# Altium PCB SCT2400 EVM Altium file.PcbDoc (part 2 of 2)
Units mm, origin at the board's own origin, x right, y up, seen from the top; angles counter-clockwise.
Board outline 45.2 x 80.2 mm, 4 copper layers (Top Layer, Signal Layer 1, Signal Layer 2, Bottom Layer), stack 0.778 mm thick; 165 components, 146 nets, 619 pads, 674 vias.
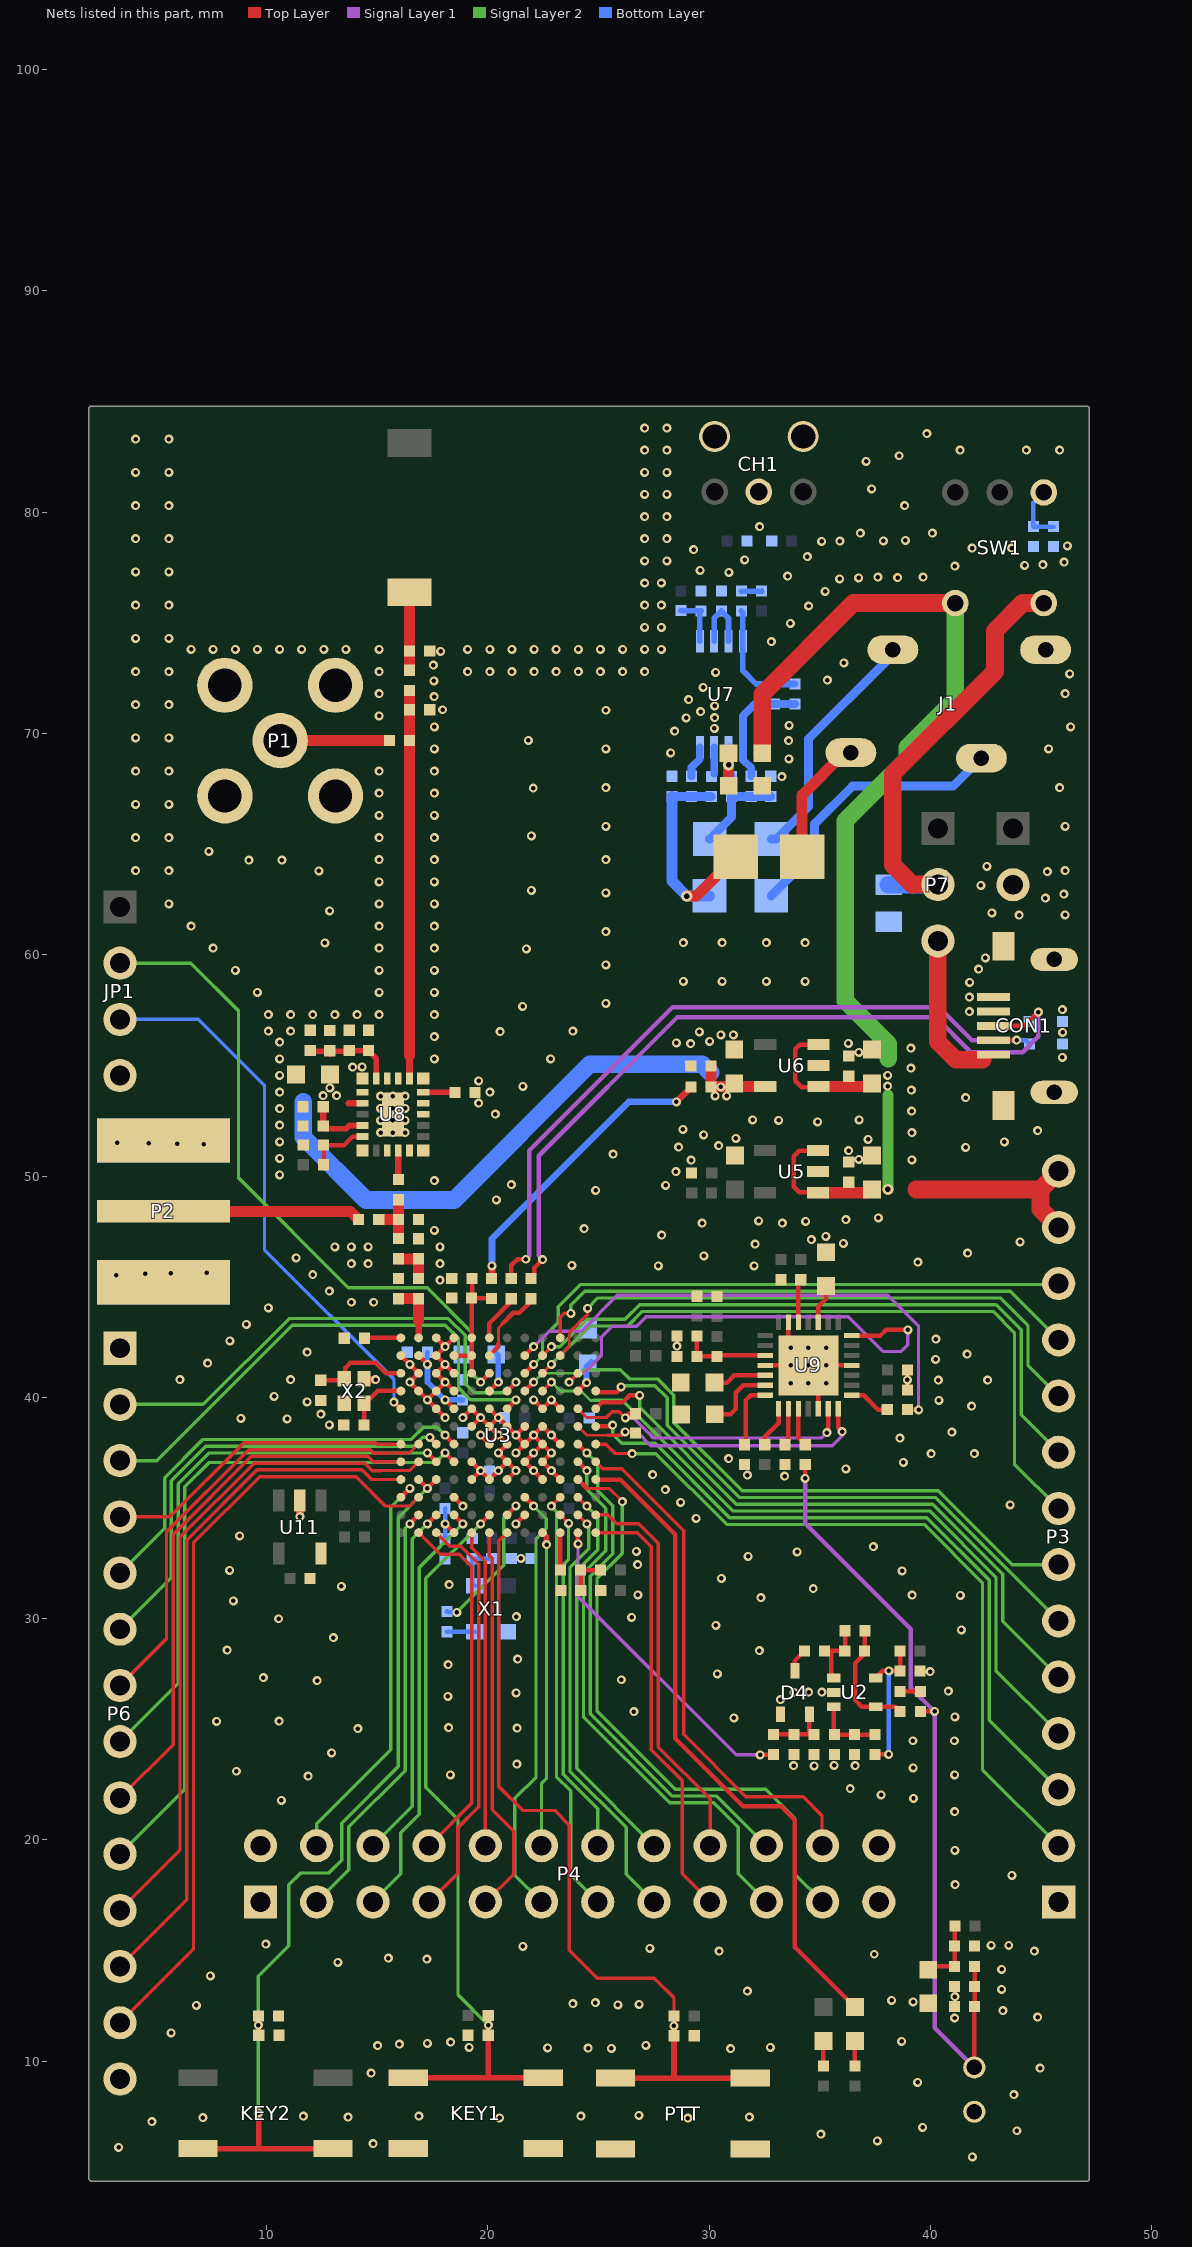
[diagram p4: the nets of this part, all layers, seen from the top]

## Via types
v1: diameter 0.406, hole 0.203, Top Layer to Bottom Layer, tented both sides, 667 vias
v2: diameter 0.406, hole 0.203, Top Layer to Bottom Layer, tented top, 4 vias
v3: diameter 0.508, hole 0.254, Top Layer to Bottom Layer, tented both sides, 3 vias

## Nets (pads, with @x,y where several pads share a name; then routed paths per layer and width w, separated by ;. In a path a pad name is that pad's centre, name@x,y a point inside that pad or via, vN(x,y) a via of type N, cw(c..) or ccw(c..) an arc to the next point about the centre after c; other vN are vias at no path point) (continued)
GND: C2.2 C3.1 C4.2 C7.1 C9.1 C11.1 C12.1 C13.2 C16.2 C17.1 C18.2 C19.2 C21.2 C22.1 C23.2 C24.2 C25.2 C26.2 C27.2 C28.2 C29.2 C31.2 C32.2 C33.2 C34.1 C35.2 C36.2 C37.1 C39.2 C41.1 C43.2 C50.2 C53.2 C54.2 C55.2 C56.2 C57.2 C58.2 C59.2 C60.1 C61.1 C66.1 C67.1 C68.1 C69.1 C70.1 C71.2 C72.1 C73.2 C74.1 C75.2 C76.2 C77.1 C78.2 C88.2 C89.2 C90.2 C95.2 C96.2 C97.1 C99.1 C100.2 C104.2 C105.2 C106.1 C107.2 C108.1 C111.1 C112.1 C113.2 C114.1 C115.1 CH1.2 CH1.4 CH1.5 CON1.4 CON1.5 CON1.6 D2.1 D3.1 D4.1 DC5V.2 J1.1 JP1.4 KEY1.2 MIC1.2 P1.2 P2.2 P3.1 P4.1 P4.2 P4.23 P4.24 P6.1 P6.14 PTT.2 R3.2 R4.2 R12.1 R24.2 R34.1 R40.1 U2.2 U3.A11 U3.B9 U3.B10 U3.C8 U3.C9 U3.C10 U3.C11 U3.C12 U3.D3 U3.D9 U3.D10 U3.D12 U3.E4 U3.E5 U3.E7 U3.E8 U3.F4 U3.F6 U3.F7 U3.F8 U3.G4 U3.G5 U3.G6 U3.G7 U3.H2 U3.H5 U3.H6 U3.H7 U3.J4 U3.J5 U3.J6 U3.J7 U3.J8 U3.K4 U3.K6 U3.K8 U5.2 U6.2 U7.7 U8.0 U8.1 U8.4 U8.5 U8.7 U8.9 U8.10 U8.12 U8.13 U8.18 U8.20 U8.22 U9.4 U9.13 U9.18 U9.26 U9.29 U11.2 U11.5 X1.2 X2.2 X2.4 | length 44.1
  Top Layer w0.203: U3.A11@16.068,41.888 v1(16.468,41.488) U3.B10@16.868,41.088 v1(16.468,40.688) U3.B9@16.868,40.288 v1(17.268,39.888) ; U3.C12@17.668,42.688 v1(18.068,42.288) ; v1(18.068,39.088) U3.C8@17.668,39.488 v1(17.268,39.888) ; U3.D3@18.468,35.488 v1(18.868,35.088) ; U3.D9@18.468,40.288 v1(18.068,40.688) ; U3.D10@18.468,41.088 v1(18.068,41.488) ; U3.D12@18.468,42.688 v1(18.068,42.288) ; v1(18.868,39.088) U3.E8@19.268,39.488 v1(19.668,39.088) ; U3.E4@19.268,36.288 v1(19.668,36.688) ; U3.E5@19.268,37.088 v1(19.668,36.688) ; U3.E7@19.268,38.688 v1(19.668,39.088) ; v1(19.668,38.288) U3.F6@20.068,37.888 v1(20.468,38.288) ; U3.F8@20.068,39.488 v1(20.468,39.088) ; U3.G4@20.868,36.288 v1(21.268,36.688) v1(20.468,37.488) U3.G6@20.868,37.888 v1(20.468,38.288) ; U3.G5@20.868,37.088 v1(20.468,36.688) U3.F4@20.068,36.288 v1(19.668,36.688) ; v1(21.268,34.288) U3.H2@21.668,34.688 ; v1(21.268,37.488) U3.H6@21.668,37.888 ; U3.H7@21.668,38.688 v1(21.268,38.288) ; v1(22.068,39.888) U3.J8@22.468,39.488 v1(22.868,39.888) ; U3.J4@22.468,36.288 v1(22.068,36.688) U3.H5@21.668,37.088 v1(22.068,37.488) U3.J6@22.468,37.888 ; v1(22.868,37.488) U3.J5@22.468,37.088 v1(22.868,36.688) U3.K4@23.268,36.288 ; v1(22.868,37.488) U3.J6@22.468,37.888 ; v1(22.868,39.888) U3.K8@23.268,39.488 ; U3.K6@23.268,37.888 v1(22.868,38.288) U3.J7@22.468,38.688 v1(22.068,38.288) ; U9.18@32.53,41.444 v1(34.48,41.444) ; U9.13@33.58,43.394 33.58,42.344 v1(34.48,41.444) ; U9.26@34.93,39.494 34.93,40.994 v1(34.48,41.444) ; U9.4@36.43,41.444 v1(34.48,41.444) ; v1(17.268,39.888) U3.C9@17.668,40.288 v1(18.068,40.688) ; v1(18.068,40.688) U3.C10@17.668,41.088 v1(18.068,41.488) ; v1(18.068,41.488) U3.C11@17.668,41.888 v1(18.068,42.288) ; v1(19.668,39.088) U3.F7@20.068,38.688 ; U3.F7@20.068,38.688 v1(20.468,38.288) ; U3.F7@20.068,38.688 v1(20.468,39.088) ; v1(20.468,39.088) U3.G7@20.868,38.688 v1(21.268,38.288) ; v1(21.268,38.288) U3.H6@21.668,37.888 ; U3.H6@21.668,37.888 v1(22.068,38.288) ; v1(22.068,38.288) U3.J6@22.468,37.888
  Top Layer w0.35: v1(11.506,34.613) U11.2@11.506,35.334 ; X2.2@14.439,40.801 v1(14.925,40.801)
  Bottom Layer w0.35: C50.2@30.222,68.181 U7.7@30.222,69.372
  other v1: 41.885,5.686 3.316,6.111 14.817,6.279 37.598,6.405 35.045,6.709 43.901,6.861 39.645,7.014 4.816,7.277 20.533,7.439 29.035,7.429 7.116,7.459 13.683,7.479 31.812,7.479 11.656,7.52 16.885,7.52 24.202,7.52 26.816,7.561 43.77,8.493 39.412,9.05 14.728,9.46 44.955,9.689 25.582,10.587 30.967,10.576 22.698,10.605 24.53,10.593 19.152,10.623 32.76,10.631 15.012,10.71 27.142,10.716 15.996,10.778 17.259,10.809 18.317,10.871 38.693,10.894 5.687,11.28 41.089,11.956 44.834,11.999 43.271,12.288 6.822,12.526 25.867,12.554 26.832,12.573 23.843,12.604 24.852,12.65 39.215,12.683 38.247,12.749 41.097,12.924 31.721,13.175 43.21,13.245 7.461,13.864 43.216,14.158 13.217,14.472 17.238,14.621 15.499,14.665 37.456,14.836 30.444,14.978 44.692,14.978 27.323,15.1 21.574,15.193 42.742,15.242 43.534,15.243 9.964,15.292 41.115,17.988 43.678,18.404 41.104,19.528 41.084,21.281 10.663,21.788 39.23,21.879 37.77,22.042 36.372,22.325 11.879,22.883 18.304,22.943 41.084,22.943 8.636,23.106 39.21,23.253 33.813,23.364 34.741,23.349 36.595,23.359 35.642,23.369 21.303,23.43 12.933,23.936 39.199,24.484 41.074,24.484 14.129,25.031 21.324,25.051 18.223,25.071 7.745,25.355 10.562,25.375 31.113,25.517 41.094,25.568 26.593,25.801 33.215,26.338 18.192,26.49 21.273,26.642 33.823,26.667 34.487,26.683 35.095,26.683 40.806,26.728 12.285,27.2 26.026,27.24 9.853,27.342 30.363,27.504 39.984,27.608 18.202,27.929 21.344,28.172 32.268,28.557 8.211,28.578 13.014,29.145 41.388,29.49 30.302,29.692 10.541,29.996 26.492,30.057 21.283,30.088 8.501,30.809 32.329,30.949 39.169,31.06 41.348,31.05 26.774,31.078 34.7,31.354 13.379,31.456 18.248,31.542 30.545,31.82 38.713,32.165 8.332,32.185 26.764,32.447 21.488,32.72 31.761,32.814 33.97,33.016 26.703,33.044 37.416,33.259 8.778,33.746 29.407,34.536 43.597,35.144 28.707,35.26 28.014,35.836 33.405,36.442 31.718,36.485 27.445,36.51 36.179,36.765 38.775,37.06 30.878,37.23 40.03,37.455 41.976,37.455 38.611,38.16 40.962,38.428 12.835,38.753 10.922,39.03 8.834,39.048 12.453,39.238 41.854,39.603 11.834,39.798 40.375,39.867 10.334,40.048 33.68,40.644 34.48,40.644 35.28,40.644 38.951,40.786 40.355,40.779 42.584,40.779 6.084,40.798 11.084,40.798 33.68,41.444 35.28,41.444 7.334,41.548 40.233,41.721 41.652,41.954 11.834,42.048 33.68,42.244 34.48,42.244 35.28,42.244 28.543,42.318 8.334,42.548 40.243,42.633 9.084,43.298 10.084,44.048 13.834,44.298 14.834,44.298 12.834,44.798 17.834,45.298 3.215,45.521 12.084,45.548 4.522,45.592 5.677,45.612 7.299,45.622 32.025,45.937 23.796,45.967 27.699,45.946 13.834,46.048 14.584,46.048 17.834,46.048 39.422,46.109 11.334,46.298 29.755,46.393 41.672,46.514 13.084,46.798 13.834,46.798 14.584,46.798 17.834,46.798 32.076,46.929 36.058,46.96 44.043,47.021 34.614,47.127 35.273,47.269 27.853,47.333 17.584,47.548 24.343,47.629 29.674,47.872 33.306,47.878 32.227,47.973 34.355,47.953 36.179,48.034 37.639,48.115 20.386,48.923 24.87,49.352 28.029,49.584 21.058,49.611 17.584,49.798 10.584,50.048 28.488,50.203 29.187,50.725 39.159,50.73 36.762,50.755 10.584,50.798 25.661,50.993 36.301,51.15 41.584,51.298 28.62,51.307 30.424,51.378 7.157,51.439 4.684,51.48 5.961,51.459 3.245,51.5 10.584,51.548 43.334,51.548 37.178,51.657 31.204,51.703 29.744,51.865 15.155,51.961 15.705,51.961 16.255,51.961 39.159,51.966 44.834,52.048 28.812,52.108 10.584,52.298 34.893,52.453 15.155,52.511 15.705,52.511 16.255,52.511 33.139,52.513 31.964,52.534 36.767,52.544 20.334,52.798 39.144,52.934 10.584,53.048 15.155,53.061 15.705,53.061 16.255,53.061 19.584,53.298 41.584,53.548 15.155,53.611 15.705,53.611 16.255,53.611 10.584,53.798 20.084,53.798 39.138,53.887 21.584,54.048 19.584,54.298 10.584,54.548 39.113,54.874 13.885,54.925 14.317,54.931 10.584,55.298 17.584,55.298 22.834,55.298 45.959,55.361 36.757,55.589 39.108,55.781 29.163,55.983 36.286,55.994 28.519,56.016 10.584,56.048 30.021,56.082 17.584,56.298 30.53,56.377 31.092,56.374 45.963,56.496 20.551,56.528 29.559,56.517 10.084,56.548 11.084,56.548 23.834,56.548 10.084,57.298 11.084,57.298 12.084,57.298 13.084,57.298 14.084,57.298 15.084,57.298 17.584,57.298 41.756,57.434 45.959,57.524 21.564,57.672 25.334,57.798 41.759,58.084 9.584,58.298 15.084,58.298 17.584,58.298 41.77,58.754 28.834,58.798 30.584,58.798 32.584,58.798 34.334,58.798 8.584,59.298 15.084,59.298 17.584,59.298 42.177,59.351 25.334,59.548 42.479,59.857 21.739,60.269 7.584,60.298 15.084,60.298 17.584,60.298 12.628,60.534 28.834,60.548 30.584,60.548 32.584,60.548 34.334,60.548 25.334,61.048 6.584,61.298 15.084,61.298 17.584,61.298 44.003,61.786 46.084,61.798 42.766,61.897 12.848,61.986 5.584,62.298 15.084,62.298 17.584,62.298 45.188,62.556 46.019,62.738 25.334,62.798 21.96,62.911 42.27,63.134 15.084,63.298 17.584,63.298 45.28,63.762 4.084,63.798 5.584,63.798 12.364,63.791 46.084,63.798 42.543,63.995 9.194,64.275 10.691,64.275 15.084,64.298 17.584,64.298 25.334,64.298 7.389,64.671 4.084,65.298 5.584,65.298 15.084,65.298 17.584,65.298 21.96,65.376 25.334,65.798 46.084,65.798 15.084,66.298 17.584,66.298 4.084,66.798 5.584,66.798 15.084,67.298 17.584,67.298 22.048,67.533 25.334,67.548 45.834,67.548 33.284,68.049 4.084,68.298 5.584,68.298 15.084,68.298 17.584,68.298 33.603,68.848 28.26,69.123 17.584,69.298 25.334,69.298 45.334,69.298 21.828,69.69 33.586,69.678 4.084,69.798 5.584,69.798 28.436,70.102 30.232,70.226 17.584,70.298 46.334,70.298 33.614,70.366 28.953,70.702 30.238,70.712 15.084,70.798 29.608,70.983 25.334,71.048 17.954,71.071 30.238,71.244 4.084,71.298 5.584,71.298 29.069,71.527 17.564,71.661 15.084,71.798 46.084,71.798 29.729,72.083 17.554,72.375 35.342,72.408 46.286,72.694 30.29,72.76 4.084,72.798 5.584,72.798 15.084,72.798 19.084,72.798 20.084,72.798 21.084,72.798 22.084,72.798 23.084,72.798 24.084,72.798 25.084,72.798 26.084,72.798 27.084,72.798 17.539,73.09 36.079,73.189 17.858,73.708 6.584,73.798 7.584,73.798 8.584,73.798 9.584,73.798 10.584,73.798 11.584,73.798 12.584,73.798 13.584,73.798 15.084,73.798 19.084,73.798 20.084,73.798 21.084,73.798 22.084,73.798 23.084,73.798 24.084,73.798 25.084,73.798 26.084,73.798 27.084,73.798 27.834,73.798 32.811,74.147 4.084,74.298 5.584,74.298 27.084,74.798 27.834,74.798 33.669,74.972 34.489,75.759 4.084,75.798 5.584,75.798 27.084,75.798 27.834,75.798 35.232,76.425 27.084,76.798 27.834,76.798 35.887,76.981 36.751,77.03 38.517,77.041 37.62,77.068 39.667,77.069 33.537,77.112 30.885,77.283 4.084,77.298 5.584,77.298 29.592,77.366 41.097,77.558 44.256,77.597 45.081,77.63 46.033,77.74 27.084,77.798 28.084,77.798 31.6,77.844 34.439,77.987 29.295,78.307 41.879,78.373 43.662,78.373 46.187,78.472 35.083,78.675 35.903,78.692 37.873,78.703 38.863,78.725 4.084,78.798 5.584,78.798 27.084,78.798 28.084,78.798 36.834,79.048 40.084,79.048 32.271,79.346 27.084,79.798 28.084,79.798 4.084,80.298 5.584,80.298 38.834,80.298 27.084,80.798 28.084,80.798 37.334,81.048 4.084,81.798 5.584,81.798 27.084,81.798 28.084,81.798 37.084,82.298 38.584,82.548 27.084,82.798 28.084,82.798 41.334,82.798 44.334,82.798 45.834,82.798 4.084,83.298 5.584,83.298 39.834,83.548 27.084,83.798 28.084,83.798
IIC_SCK: R19.2 U3.L7 U9.28 | length 14.4
  Top Layer w0.127: U3.L7@24.068,38.688 24.471,38.285 25.395,38.285
  Top Layer w0.152: 25.395,38.285 26.052,38.285 v1(26.203,38.436)
  Top Layer w0.203: v1(26.203,38.436) 26.623,38.436 R19.2@26.669,38.39 ; U9.28@35.83,39.494 35.83,38.625 v1(36.005,38.451)
  Signal Layer 1 w0.152: v1(26.203,38.436) 26.741,38.436 27.358,37.819 35.557,37.819 36.005,38.267 v1(36.005,38.451)
IIC_SDA: R20.2 U3.L8 U9.27 | length 13.8
  Top Layer w0.127: U3.L8@24.068,39.488 24.466,39.09 25.188,39.09
  Top Layer w0.152: 25.188,39.09 25.352,39.09 25.608,39.346 25.934,39.346 v1(26.21,39.069)
  Top Layer w0.203: v1(35.32,38.403) 35.38,38.464 U9.27@35.38,39.494
  Top Layer w0.254: v1(26.21,39.069) 26.396,39.254 R20.2@26.665,39.254
  Signal Layer 1 w0.152: v1(26.21,39.069) 26.574,39.069 27.476,38.167 35.084,38.167 v1(35.32,38.403)
IN1L: C10.2 U9.24 | length 1.8
  Top Layer w0.203: U9.24@34.03,39.494 34.03,38.165 C10.2@34.338,37.858
KEY1: C89.1 KEY1.1 R13.1 U3.F2 | length 34.3
  Top Layer w0.203: v1(19.668,34.288) U3.F2@20.068,34.688
  Top Layer w0.254: KEY1.1@16.406,9.257 20.026,9.257 ; R13.1@20.011,12.068 C89.1@20.011,11.179 20.011,9.271 20.026,9.257 ; KEY1.1@22.502,9.257 20.026,9.257
  Signal Layer 2 w0.152: v1(19.668,34.288) 17.196,31.817 17.196,22.377 18.649,20.924 18.649,12.995 v1(20.015,11.629)
KEY2: C88.1 KEY2.1 R12.2 U3.B4 U3.C4 | length 42.1
  Top Layer w0.152: R12.2@9.627,11.192 R12.2@9.639,11.18
  Top Layer w0.203: U3.B4@16.868,36.288 v1(17.268,35.888) U3.C4@17.668,36.288
  Top Layer w0.254: KEY2.1@6.902,6.054 KEY2.1@12.998,6.054 ; v1@9.626,11.626 9.626,12.045 C88.1@9.627,12.047 R12.2@9.627,11.192 ; 9.637,6.169 v1(9.637,7.67)
  Signal Layer 2 w0.152: v1@9.624,7.683 v1(9.624,11.631) 9.624,13.845 11.002,15.223 11.002,17.977 11.533,18.508 12.817,18.508 13.387,19.078 13.387,20.762 15.944,23.32 15.944,34.565 v1(17.268,35.888)
MCLK: R5.1 U3.H11 | length 23.8
  Top Layer w0.203: U3.H11@21.668,41.888 v1(22.068,42.288) ; R5.1@38.96,39.447 38.973,39.434 v1(39.458,39.434)
  Signal Layer 1 w0.152: v1(22.068,42.288) 22.775,42.996 24.233,42.996 25.846,44.609 38.072,44.609 39.458,43.223 v1(39.458,39.434)
MCLK1: C15.1 U3.G2 | length 7
  Top Layer w0.203: U3.G2@20.868,34.688 21.268,35.088 v1(21.268,35.101)
  Signal Layer 2 w0.152: v1(18.601,30.29) 20.718,32.406 20.718,34.551 v1(21.268,35.101)
  Bottom Layer w0.203: C15.1@18.149,30.324 18.169,30.343 18.222,30.29 v1(18.601,30.29)
MIC: C10.1 C18.1 C38.2 C115.2 MIC1.1 R32.2 | length 35.6
  Top Layer w0.203: v1(34.328,36.34) 34.328,36.949 C10.1@34.338,36.958 ; C38.2@39.539,25.812 39.546,25.806 v1(40.182,25.806) ; MIC1.1@41.977,9.72 C18.1@41.977,12.469 41.988,12.48 C115.2@41.988,13.377 R32.2@41.988,14.292
  Signal Layer 1 w0.203: v1(34.328,36.34) 34.328,34.307 39.103,29.532 39.103,26.885 v1(40.182,25.806) 40.182,11.514 MIC1.1@41.977,9.72
NetB5_1: B5.1 C50.1 C70.2 U7.6 | length 2.8
  Top Layer w0.5: B5.1@30.875,69.103 v3(30.875,68.584) 30.875,67.637 C70.2@30.878,67.634
  Bottom Layer w0.35: U7.6@30.872,69.372 30.872,68.196 C50.1@31.004,68.064
NetB6_1: B6.1 C13.1 X1.4 | length 2.2
  Bottom Layer w0.203: X1.4@19.418,31.488 19.292,31.614 C13.1@19.292,32.712 20.165,32.712 B6.1@20.171,32.719
NetB7_1: B7.1 C91.2 R21.2 U7.5 | length 5.5
  Bottom Layer w0.35: B7.1@31.893,68.064 31.893,68.445 31.522,68.816 U7.5@31.522,69.372 31.522,70.787 32.068,71.333 C91.2@32.958,71.333 33.868,71.333 R21.2@33.875,71.34
NetB7_2: B7.2 C1.1 C94.1 C96.1 | length 4.1
  Bottom Layer w0.4: C1.1@30.019,65.228 31.004,66.214 C94.1@31.004,67.149 B7.2@31.893,67.149 C96.1@32.782,67.149
NetB8_1: B8.1 U7.8 | length 1.5
  Bottom Layer w0.35: B8.1@29.201,68.064 29.201,68.471 29.572,68.842 U7.8@29.572,69.372
NetB8_2: B8.2 C20.1 C94.2 C95.1 LS1.1 | length 10.5
  Top Layer w0.5: v3(28.984,62.651) 29.42,62.651 LS1.1@31.197,64.428
  Bottom Layer w0.4: C95.1@28.312,67.149 B8.2@29.201,67.149 C94.2@30.09,67.149
  Bottom Layer w0.5: C95.1@28.312,67.149 28.312,63.323 v3(28.984,62.651) 30,62.651 C20.1@30.01,62.661
NetC1_2: C1.2 J1.4 | length 10.8
  Bottom Layer w0.4: C1.2@32.813,65.228 33.021,65.228 34.487,66.694 34.487,69.751 38.02,73.284 J1.4@38.02,73.779
NetC6_1: C6.1 D4.3 | length 1.1
  Top Layer w0.203: D4.3@33.875,27.637 33.875,28.109 C6.1@34.306,28.541
NetC6_2: C6.2 C30.1 R36.2 U2.1 | length 3.2
  Top Layer w0.203: C6.2@35.206,28.541 35.504,28.541 ; U2.1@35.627,27.322 35.621,27.315 35.621,27.295 35.504,27.412 35.504,28.541 ; C30.1@36.135,29.456 36.135,28.552 R36.2@36.124,28.541 35.504,28.541
NetC7_2: C7.2 U9.23 | length 1.7
  Top Layer w0.203: C7.2@33.423,37.858 33.58,38.015 U9.23@33.58,39.494
NetC8_2: C8.2 U9.22 | length 1.9
  Top Layer w0.203: C8.2@32.509,37.858 32.509,38.214 33.13,38.836 U9.22@33.13,39.494
NetC9_2: C9.2 U9.21 | length 3
  Top Layer w0.203: C9.2@31.594,37.858 31.641,37.904 31.641,39.862 31.873,40.094 U9.21@32.53,40.094
NetC11_2: C11.2 R1.1 R2.2 | length 1.8
  Top Layer w0.203: C11.2@24.194,31.278 24.194,32.181 R1.1@24.183,32.192 R2.2@25.086,32.192
NetC15_2: C15.2 X1.3 | length 1.3
  Bottom Layer w0.203: C15.2@18.149,29.409 X1.3@19.418,29.408 X1.3@19.418,29.408
NetC16_1: C16.1 C114.2 U3.B11 U3.D8 | length 4.4
  Top Layer w0.203: U3.B11@16.868,41.888 v1(17.268,41.488) ; v1(18.068,39.888) U3.D8@18.468,39.488
  Bottom Layer w0.203: v1(17.268,41.488) 17.268,42.035 C114.2@17.274,42.042
  Bottom Layer w0.254: v1(17.268,41.488) 17.268,40.688 v1(18.068,39.888) 18.844,39.888 C16.1@18.849,39.883
NetC17_2: C17.2 U3.A12 | length 1.7
  Top Layer w0.203: C17.2@14.42,42.668 14.44,42.688 U3.A12@16.068,42.688
NetC19_1: C19.1 R26.2 U8.17 | length 2.8
  Top Layer w0.203: R26.2@12.57,50.512 C19.1@12.57,51.401 13.508,51.401 13.893,51.786 U8.17@14.33,51.786
NetC20_2: C20.2 J1.2 | length 12.8
  Bottom Layer w0.4: C20.2@32.804,62.661 34.751,64.608 34.751,65.901 36.477,67.627 41.018,67.627 J1.2@42.27,68.879
NetC22_2: C22.2 U3.F9 | length 1.8
  Top Layer w0.203: U3.F9@20.068,40.288 v1(20.468,40.688)
  Bottom Layer w0.254: C22.2@20.422,41.938 20.468,41.893 v1(20.468,40.688)
NetC24_1: C24.1 D4.2 R11.2 R24.1 | length 2.5
  Top Layer w0.203: R11.2@32.909,24.768 34.481,24.768 34.525,24.811 D4.2@34.525,25.687
NetC30_2: C30.2 R36.1 R39.2 U2.4 | length 5.6
  Top Layer w0.203: C30.2@37.035,29.456 37.035,28.552 R36.1@37.024,28.541 37.024,28.417 36.588,27.981 36.588,26.324 36.89,26.022 U2.4@37.527,26.022 38.415,26.022 R39.2@38.624,25.812
NetC32_1: C32.1 R37.1 R38.2 U2.5 | length 6.6
  Top Layer w0.203: R38.2@37.481,23.857 37.489,23.864 v1(38.104,23.864) ; U2.5@37.527,27.322 37.847,27.642 v1(38.113,27.642) 38.609,27.642 C32.1@38.624,27.627 R37.1@38.624,28.541
  Bottom Layer w0.203: v1(38.104,23.864) 38.113,23.873 v1(38.113,27.642)
NetC36_1: C36.1 R38.1 R40.2 U2.3 | length 3.1
  Top Layer w0.203: U2.3@35.627,26.022 35.627,24.782 C36.1@35.653,24.757 R38.1@37.481,24.757
NetC38_1: C38.1 R39.1 | length 0.9
  Top Layer w0.203: R39.1@38.624,26.712 C38.1@39.539,26.712
NetC39_1: C39.1 U7.2 U7.3 | length 3
  Bottom Layer w0.254: U7.2@30.222,74.172 30.222,75.206 C39.1@30.547,75.531 30.872,75.206 U7.3@30.872,74.172
NetC41_2: C41.2 U3.L9 | length 1.6
  Top Layer w0.203: U3.L9@24.068,40.288 24.442,40.663 v1(24.456,40.663)
  Bottom Layer w0.254: v1(24.456,40.663) 24.456,41.39 C41.2@24.68,41.614
NetC43_1: C43.1 R18.2 U3.D1 | length 1.9
  Top Layer w0.203: v1(18.068,34.288) U3.D1@18.468,33.888
  Bottom Layer w0.203: C43.1@18.062,33.609 18.068,33.615 v1(18.068,34.288) 18.068,34.975 R18.2@18.062,34.981
NetC51_2: C51.2 R22.1 | length 0.9
  Bottom Layer w0.254: R22.1@31.45,76.431 32.359,76.431 C51.2@32.366,76.438
NetC54_1: C54.1 R23.2 U7.1 | length 2.3
  Bottom Layer w0.254: R23.2@28.718,75.546 29.618,75.546 C54.1@29.633,75.531 29.572,75.471 U7.1@29.572,74.172
NetC57_1: C57.1 C74.2 R28.1 U9.17 | length 4
  Top Layer w0.203: C57.1@29.442,42.767 29.445,42.764 C74.2@29.445,41.85 29.45,41.855 R28.1@30.35,41.855 30.389,41.894 U9.17@32.53,41.894
NetC59_1: C59.1 C76.1 R31.2 R32.1 | length 3.1
  Top Layer w0.203: C76.1@39.894,14.139 40.047,14.292 R32.1@41.088,14.292 41.103,14.306 R31.2@41.103,16.121
NetC60_2: C60.2 C61.2 R33.2 U3.D11 U3.E10 U3.E11 U3.E12 | length 8.4
  Top Layer w0.203: C60.2@19.281,45.375 19.281,44.5 C61.2@19.266,44.486 C61.2@19.268,44.485 ; R33.2@20.17,44.475 19.277,44.475 C61.2@19.268,44.485 ; U3.E11@19.268,41.888 U3.E10@19.268,41.088 U3.E11@19.268,41.888 ; U3.E11@19.268,41.888 U3.E12@19.268,42.688 ; U3.E11@19.268,41.888 U3.D11@18.468,41.888 U3.E11@19.268,41.888 ; U3.E11@19.268,41.888 U3.E12@19.268,42.688 ; U3.E12@19.268,42.688 C61.2@19.268,44.485
NetC71_1: C71.1 U9.20 | length 3.2
  Top Layer w0.203: C71.1@30.254,39.234 30.961,39.234 31.202,39.474 31.202,40.209 31.537,40.544 U9.20@32.53,40.544
NetC72_2: C72.2 U9.19 | length 2.4
  Top Layer w0.203: C72.2@30.24,40.674 30.262,40.651 30.79,40.651 31.132,40.994 U9.19@32.53,40.994
NetC78_1: C78.1 U9.10 | length 1.8
  Top Layer w0.203: U9.10@34.93,43.394 34.93,44.107 35.277,44.454 C78.1@35.277,45.035
NetC91_1: C91.1 R21.1 R22.2 U7.4 | length 5.3
  Bottom Layer w0.254: R22.2@31.45,75.531 31.522,75.459 U7.4@31.522,74.172 31.522,72.833 32.122,72.233 C91.1@32.958,72.233
  Bottom Layer w0.305: C91.1@32.958,72.233 33.868,72.233 R21.1@33.875,72.24
NetC112_2: C112.2 U3.A10 X2.3 | length 4.4
  Top Layer w0.203: C112.2@12.448,40.778 13.445,40.778 X2.3@13.504,40.836 13.551,40.883 13.551,41.33 13.777,41.556 14.931,41.556 15.398,41.088 U3.A10@16.068,41.088
NetC113_1: C113.1 U3.A9 X2.1 | length 2.8
  Top Layer w0.203: C113.1@14.404,38.746 14.404,39.664 15.029,40.288 U3.A9@16.068,40.288
NetCON1_2: CON1.2 D3.2 R8.2 | length 33.4
  Top Layer w0.203: R8.2@21.059,45.375 21.059,45.966 21.334,46.241 v1(21.711,46.241) ; CON1.2@42.842,56.136 43.885,56.136 v1(43.892,56.143)
  Signal Layer 1 w0.203: v1(21.711,46.241) 21.862,46.392 21.862,51.153 28.347,57.637 40.377,57.637 41.871,56.143 v1(43.892,56.143)
  Bottom Layer w0.203: v1(43.892,56.143) 44.295,56.143 D3.2@44.465,55.973
NetCON1_3: CON1.3 D2.2 R10.2 | length 36
  Top Layer w0.203: R10.2@21.948,45.375 21.925,45.398 22.092,45.566 22.092,45.847 v1(22.467,46.221) ; CON1.3@42.842,56.786 44.244,56.786 v1(44.869,57.411)
  Signal Layer 1 w0.203: v1(22.467,46.221) 22.293,46.395 22.293,50.913 28.564,57.184 40.233,57.184 41.822,55.595 44.16,55.595 44.869,56.304 v1(44.869,57.411)
  Bottom Layer w0.203: D2.2@44.458,56.987 44.458,57 v1(44.869,57.411)
NetDS1_1: DS1.1 R16.1 | length 1.1
  Top Layer w0.203: R16.1@35.158,9.784 DS1.1@35.158,10.927
NetDS2_1: DS2.1 R17.1 | length 1.1
  Top Layer w0.203: R17.1@36.581,9.784 DS2.1@36.581,10.927
NetJ1_3: J1.3 LS1.2 | length 5.5
  Top Layer w0.5: LS1.2@34.197,64.427 34.197,67.206 J1.3@36.12,69.129
NetP1_1: P1.1 RC1.1 | length 4.9
  Top Layer w0.5: P1.1@10.612,69.675 RC1.1@15.557,69.674
NetR1_2: R1.2 U3.K1 | length 1.7
  Top Layer w0.203: U3.K1@23.268,33.888 23.268,32.208 R1.2@23.283,32.192
NetR3_1: R3.1 R4.1 SW1.1 | length 2.6
  Bottom Layer w0.203: SW1.1@45.12,80.891 44.651,80.421 R3.1@44.651,79.35 45.55,79.35 R4.1@45.559,79.341
NetR5_2: R5.2 U9.1 | length 1.9
  Top Layer w0.203: U9.1@36.43,40.094 36.982,40.094 37.629,39.447 R5.2@38.046,39.447
NetR8_1: R8.1 U3.F12 | length 2.2
  Top Layer w0.203: U3.F12@20.068,42.688 20.068,43.355 21.059,44.347 R8.1@21.059,44.461
NetR10_1: R10.1 U3.F11 | length 3.7
  Top Layer w0.127: U3.F11@20.068,41.888 U3.F11@20.092,41.888 ; 20.471,42.413 20.471,43.14 20.695,43.363
  Top Layer w0.203: U3.F11@20.068,41.888 20.471,42.292 20.471,42.413 ; 20.695,43.363 21.149,43.818 21.423,43.818 22.066,44.461 R10.1@21.948,44.461
NetR29_1: R29.1 U9.12 | length 2
  Top Layer w0.203: U9.12@34.03,43.394 34.03,45.211 R29.1@34.134,45.315
NetR34_2: R34.2 U8.6 | length 1.4
  Top Layer w0.203: R34.2@18.504,53.786 R34.2@18.508,53.782
  Top Layer w0.254: U8.6@17.08,53.786 R34.2@18.504,53.786
PA0: P4.12 U3.J1 | length 14.3
  Top Layer w0.254: U3.J1@22.468,33.888 22.649,33.707 v1(22.649,33.349)
  Signal Layer 2 w0.152: P4.12@22.422,19.741 22.422,22.559 22.649,22.785 v1(22.649,33.349)
PA1: P4.14 U3.K2 | length 15.9
  Top Layer w0.127: U3.K2@23.268,34.688 v1@23.677,34.279
  Signal Layer 2 w0.152: v1(23.649,34.302) 23.639,34.293 23.639,32.662 23.402,32.425 23.402,22.978 24.962,21.418 P4.14@24.962,19.741
PA2: P4.13 U3.K3 | length 19.3
  Top Layer w0.127: v1(22.862,35.083) U3.K3@23.268,35.488
  Signal Layer 2 w0.152: v1(22.862,35.083) 23.097,34.848 23.097,22.852 23.735,22.214 23.735,18.428 P4.13@24.962,17.201
PA5: P4.15 U3.L2 | length 19.6
  Top Layer w0.152: U3.L2@24.068,34.688 v1(24.468,34.288)
  Signal Layer 2 w0.152: v1(24.468,34.288) 24.561,34.195 24.561,33.153 23.707,32.299 23.707,23.105 26.246,20.565 26.246,18.456 P4.15@27.502,17.201
PA6: P4.16 U3.L3 | length 18
  Top Layer w0.152: U3.L3@24.068,35.488 v1(24.468,35.088)
  Signal Layer 2 w0.152: v1(24.468,35.088) 24.957,34.599 24.957,33.118 24.012,32.173 24.012,23.231 P4.16@27.502,19.741
PA7: P4.17 U3.M1 | length 19.9
  Top Layer w0.152: U3.M1@24.868,33.888 26.747,33.888 27.384,33.251 27.384,24.081 28.777,22.688 28.777,18.466 P4.17@30.042,17.201
PA9: P6.3 U3.G8 | length 23.7
  Top Layer w0.203: U3.G8@20.868,39.488 v1(21.268,39.888)
  Signal Layer 2 w0.152: P6.3@3.372,37.141 5.038,37.141 11.154,43.257 18.074,43.257 18.67,42.661 18.67,40.428 19.21,39.888 v1(21.268,39.888)
PA10: P6.2 U3.G9 | length 22.9
  Top Layer w0.203: U3.G9@20.868,40.288 v1(21.268,40.688)
  Signal Layer 2 w0.152: P6.2@3.372,39.681 7.147,39.681 11.028,43.562 18.217,43.562 18.975,42.803 18.975,40.614 19.385,40.205 20.784,40.205 v1(21.268,40.688)
PB2: P4.22 U3.M5 | length 23.6
  Top Layer w0.152: U3.M5@24.868,37.088 25.185,36.771 26.046,36.771 28.84,33.977 28.84,24.77 31.651,21.959 34.239,21.959 35.093,21.105 35.093,19.77 P4.22@35.122,19.741
PB3: P6.4 U3.A6 | length 14.1
  Top Layer w0.152: P6.4@3.372,34.601 5.633,34.601 8.977,37.945 14.922,37.945 14.978,37.888 U3.A6@16.068,37.888
PB4: P6.10 U3.D5 | length 30.8
  Top Layer w0.203: v1(18.068,37.488) U3.D5@18.468,37.088
  Signal Layer 2 w0.152: P6.10@3.372,19.361 6.308,22.296 6.308,35.961 7.404,37.057 17.636,37.057 v1(18.068,37.488)
PB5: P6.8 U3.C5 | length 25.1
  Top Layer w0.203: v1(17.268,37.488) U3.C5@17.668,37.088
  Signal Layer 2 w0.152: P6.8@3.372,24.441 6.003,27.071 6.003,36.087 7.405,37.488 v1(17.268,37.488)
PB6: P6.11 U3.B5 | length 30.5
  Top Layer w0.127: 15.157,36.69 16.469,36.69 U3.B5@16.868,37.088
  Top Layer w0.152: P6.11@3.372,16.821 6.085,19.533 6.085,33.676 9.439,37.031 14.436,37.031 14.777,36.69 15.157,36.69
PB7: P6.9 U3.A5 | length 24.8
  Top Layer w0.152: P6.9@3.372,21.901 5.78,24.308 5.78,33.803 9.313,37.335 14.563,37.335 14.81,37.088 15.267,37.088 U3.A5@16.068,37.088
PB9: P6.12 U3.A4 | length 31.7
  Top Layer w0.152: P6.12@3.372,14.281 6.39,17.298 6.39,33.55 9.565,36.726 14.31,36.726 14.748,36.288 15.139,36.288 U3.A4@16.068,36.288
PC0: P4.11 U3.H3 | length 19.8
  Top Layer w0.203: U3.H3@21.668,35.488 v1(22.068,35.088)
  Signal Layer 2 w0.152: v1(22.068,35.088) 22.642,34.514 22.642,34.087 22.174,33.62 22.174,22.837 21.214,21.877 21.214,18.409 P4.11@22.422,17.201
PC1: P4.10 U3.E1 | length 14.4
  Top Layer w0.152: U3.E1@19.268,33.888 19.268,33.208 19.882,32.594 P4.10@19.882,19.741
PC2: P4.9 U3.F1 | length 17.7
  Top Layer w0.152: P4.9@19.882,17.201 19.911,17.201 21.167,18.456 21.167,20.392 20.187,21.371 20.187,32.735 20.068,32.855 U3.F1@20.068,33.888
PC4: P4.18 U3.M2 | length 18
  Top Layer w0.152: U3.M2@24.868,34.688 25.423,34.688 25.822,34.29 26.823,34.29 27.7,33.413 27.7,24.196 30.042,21.854 P4.18@30.042,19.741
PC5: P4.21 U3.L4 | length 27.6
  Top Layer w0.127: 24.468,35.888 25.482,35.888 v1(26.078,35.293)
  Top Layer w0.203: U3.L4@24.068,36.288 24.468,35.888
  Signal Layer 2 w0.152: v1(26.078,35.293) 26.078,32.945 24.926,31.794 24.926,25.829 28.464,22.291 32.556,22.291 33.869,20.978 33.869,18.454 P4.21@35.122,17.201
PC14: P4.8 U3.B1 | length 16.4
  Top Layer w0.152: U3.B1@16.868,33.888 17.838,32.918 18.696,32.918 19.273,32.341 19.273,21.671 P4.8@17.342,19.741
PC15: P4.7 U3.C1 | length 18.7
  Top Layer w0.152: P4.7@17.342,17.201 18.625,18.483 18.625,20.541 19.577,21.494 19.577,32.468 18.764,33.281 18.275,33.281 U3.C1@17.668,33.888
PD5: P6.5 U3.D6 | length 19.5
  Top Layer w0.203: v1(18.068,38.288) U3.D6@18.468,37.888
  Signal Layer 2 w0.152: P6.5@3.372,32.061 5.394,34.082 5.394,36.367 7.125,38.098 16.53,38.098 17.089,38.657 17.699,38.657 v1(18.068,38.288)
PD6: P6.6 U3.C6 | length 20.6
  Top Layer w0.203: v1(17.373,38.197) 17.373,38.183 U3.C6@17.668,37.888
  Signal Layer 2 w0.152: P6.6@3.372,29.521 5.698,31.847 5.698,36.241 7.251,37.793 16.661,37.793 17.065,38.197 v1(17.373,38.197)
PD7: P6.7 U3.B6 | length 21
  Top Layer w0.127: 15.398,37.481 16.46,37.481 U3.B6@16.868,37.888
  Top Layer w0.152: P6.7@3.372,26.981 5.475,29.084 5.475,33.929 9.186,37.64 14.689,37.64 14.849,37.481 15.398,37.481
PD8: P3.10 U3.K11 | length 27
  Top Layer w0.127: U3.K11@23.268,41.888 23.677,42.298 23.677,42.94 24.124,43.387
  Top Layer w0.152: 24.124,43.387 24.501,43.764 v1(24.501,44.021)
  Signal Layer 2 w0.152: v1(24.501,44.021) 24.972,44.492 43.158,44.492 44.401,43.249 44.401,41.45 P3.10@45.79,40.061
PD9: P3.11 U3.K12 | length 25.1
  Top Layer w0.152: U3.K12@23.268,42.688 23.268,43.614 23.447,43.794 v1(23.75,43.794) v1@23.75,43.806
  Signal Layer 2 w0.152: v1(23.75,43.794) 23.75,44.165 24.382,44.797 43.594,44.797 P3.11@45.79,42.601
PD10: P3.8 U3.J10 | length 31.7
  Top Layer w0.152: U3.J10@22.468,41.088 v1(22.868,41.488)
  Signal Layer 2 w0.152: v1(22.868,41.488) 24.604,43.225 26.32,43.225 26.979,43.883 42.834,43.883 43.792,42.925 43.792,36.979 P3.8@45.79,34.981
PD11: P3.4 U3.J9 | length 32.5
  Top Layer w0.152: U3.J9@22.468,40.288 v1(22.868,40.688)
  Signal Layer 2 w0.127: v1(22.868,40.688) 23.271,40.285 24.211,40.285 24.632,39.864 24.762,39.864
  Signal Layer 2 w0.152: 24.762,39.864 26.065,39.864 31.062,34.867 39.963,34.867 42.957,31.874 42.957,27.654 P3.4@45.79,24.821
PD12: P3.9 U3.J11 | length 29.3
  Top Layer w0.152: U3.J11@22.468,41.888 v1(22.868,42.288)
  Signal Layer 2 w0.152: v1(22.868,42.288) 23.237,42.288 24.478,43.529 26.194,43.529 26.852,44.188 42.96,44.188 44.096,43.051 44.096,39.214 P3.9@45.79,37.521
PD14: P3.12 U3.H10 | length 26.7
  Top Layer w0.203: U3.H10@21.668,41.088 v1(22.068,41.488)
  Signal Layer 2 w0.127: v1(22.068,41.488) 22.471,41.892 22.471,42.682 22.873,43.084
  Signal Layer 2 w0.152: 22.873,43.084 23.172,43.383 23.172,44.088 24.186,45.102 45.752,45.102 P3.12@45.79,45.141
PD15: P3.7 U3.H9 | length 28.9
  Top Layer w0.203: U3.H9@21.668,40.288 v1(22.068,40.688)
  Signal Layer 2 w0.127: v1(22.068,40.688) 22.469,41.09 24.156,41.09 24.315,41.249 24.533,41.249
  Signal Layer 2 w0.152: 24.533,41.249 25.98,41.249 26.399,40.83 27.672,40.83 28.4,40.102 28.4,38.864 31.482,35.782 40.342,35.782 43.683,32.441 P3.7@45.79,32.441
PE0: P4.4 U3.A3 | length 18.5
  Top Layer w0.203: U3.A3@16.068,35.488 v1(16.468,35.888)
  Signal Layer 2 w0.152: P4.4@12.262,19.741 12.262,20.732 15.612,24.082 15.612,35.033 v1(16.468,35.888)
PE1: P6.13 U3.B3 | length 35.2
  Top Layer w0.127: 15.759,35.088 16.468,35.088 U3.B3@16.868,35.488
  Top Layer w0.152: P6.13@3.372,11.741 6.694,15.063 6.694,33.424 9.691,36.421 14.04,36.421 15.372,35.088 15.759,35.088
PE3: P4.3 U3.B2 | length 19.4
  Top Layer w0.203: v1(16.468,34.288) U3.B2@16.868,34.688
  Signal Layer 2 w0.152: P4.3@12.262,17.201 13.715,18.654 13.715,20.588 16.265,23.138 16.265,34.086 v1(16.468,34.288)
PE4: P4.6 U3.C2 | length 16.1
  Top Layer w0.203: v1(17.268,34.288) U3.C2@17.668,34.688
  Signal Layer 2 w0.152: P4.6@14.802,19.741 16.586,21.525 16.586,33.607 v1(17.268,34.288)
PE5: P4.5 U3.D2 | length 19.3
  Top Layer w0.203: U3.D2@18.468,34.688 v1(18.868,34.288)
  Signal Layer 2 w0.152: P4.5@14.802,17.201 16.068,18.466 16.068,20.334 16.891,21.157 16.891,32.312 v1(18.868,34.288)
PE7: P3.2 U3.M6 | length 33.4
  Top Layer w0.152: U3.M6@24.868,37.888 25.333,37.888 25.759,37.463 v1(26.511,37.463)
  Signal Layer 2 w0.152: v1@26.511,37.457 27.589,37.457 30.789,34.258 39.71,34.258 42.347,31.621 42.347,23.184 P3.2@45.79,19.741
PE8: P4.19 U3.L5 | length 25.4
  Top Layer w0.203: U3.L5@24.068,37.088 v1(24.468,36.688)
  Signal Layer 2 w0.152: v1(24.468,36.688) 24.468,35.842 25.329,34.98 25.329,33.059 24.317,32.047 24.317,25.576 28.212,21.681 30.211,21.681 31.307,20.585 31.307,18.476 P4.19@32.582,17.201
PE9: P3.3 U3.M7 | length 31.7
  Top Layer w0.203: U3.M7@24.868,38.688 25.579,38.688 v1(25.638,38.747)
  Signal Layer 2 w0.152: v1(25.638,38.747) 25.638,38.336 26.049,37.924 27.553,37.924 30.915,34.563 39.837,34.563 42.652,31.747 42.652,25.419 P3.3@45.79,22.281
PE10: P3.5 U3.M8 | length 28
  Top Layer w0.203: U3.M8@24.868,39.488 25.148,39.768 26.08,39.768 26.405,40.093 v1(26.855,40.093)
  Signal Layer 2 w0.152: v1(26.855,40.093) 26.855,39.545 31.227,35.172 40.089,35.172 43.261,32 43.261,29.889 P3.5@45.79,27.361
PE11: P3.6 U3.M9 | length 26.3
  Top Layer w0.127: U3.M9@24.868,40.288 U3.M9@24.874,40.295
  Top Layer w0.203: U3.M9@24.868,40.288 24.927,40.229 25.824,40.229 26.065,40.471 v1(26.015,40.471)
  Signal Layer 2 w0.152: v1(26.015,40.471) 26.07,40.525 27.545,40.525 28.095,39.976 28.095,38.738 31.356,35.477 40.215,35.477 P3.6@45.79,29.901 P3.6@45.79,29.901
PE12: P4.20 U3.L6 | length 23.7
  Top Layer w0.203: U3.L6@24.068,37.888 v1(24.468,37.488)
  Signal Layer 2 w0.152: v1(24.468,37.488) 24.965,36.991 24.965,35.775 25.633,35.107 25.633,32.932 24.621,31.92 24.621,25.703 28.338,21.986 30.337,21.986 P4.20@32.582,19.741
POWER: C104.1 P7.2 SW1.4 | length 20
  Top Layer w0.8: P7.2@40.497,63.187 39.2,63.187 39.182,63.169 38.294,64.057 38.294,68.183 42.91,72.798 42.91,74.643 44.157,75.891 SW1.4@45.12,75.891
  Bottom Layer w0.8: C104.1@38.104,63.169 P7.2@40.333,63.169
PTT: C90.1 PTT.1 R14.1 U3.G1 | length 36.5
  Top Layer w0.152: U3.G1@20.868,33.888 20.492,33.513 20.492,22.416 21.574,21.334 23.016,21.334 23.682,20.668 23.682,15.011 24.942,13.751 27.517,13.751 28.407,12.861 R14.1@28.407,12.045
  Top Layer w0.254: PTT.1@25.762,9.238 28.401,9.238 ; R14.1@28.407,12.045 C90.1@28.407,11.156 28.407,9.245 28.401,9.238 ; PTT.1@31.858,9.238 28.401,9.238
  other v1: 28.404,11.596
R_LED: DS2.2 U3.M4 | length 30.3
  Top Layer w0.203: U3.M4@24.868,36.288 25.979,36.288 28.467,33.801 28.467,24.588 31.541,21.513 33.257,21.513 33.869,20.902 33.869,15.163 DS2.2@36.581,12.451
RF1: P2.1 RC2.2 | length 9.1
  Top Layer w0.5: P2.1@5.337,48.403 P2.1@5.417,48.403 ; P2.1@5.337,48.482 P2.1@5.417,48.403 ; RC2.2@14.15,48.042 13.789,48.403 P2.1@5.417,48.403
RF2: C101.1 C108.2 L2.2 | length 1.8
  Top Layer w0.5: C101.1@15.953,46.258 C108.2@16.868,46.258 L2.2@16.868,45.375
RF3: C101.2 C102.1 C111.2 RC2.1 | length 2.6
  Top Layer w0.5: RC2.1@15.064,48.042 C111.2@15.953,48.042 ; C101.2@15.953,47.173 C111.2@15.953,48.042 ; C102.1@15.953,48.931 C111.2@15.953,48.042
RF4: C102.2 U8.21 | length 1.2
  Top Layer w0.3: C102.2@15.955,49.948 U8.21@15.955,51.161
RF5: C105.1 RA.1 RC1.2 U8.8 | length 17.5
  Top Layer w0.3: U8.8@16.455,54.411 16.455,55.454
  Top Layer w0.5: 16.455,55.454 RA.1@16.455,71.923
RF6: C106.2 P8.1 RA.2 | length 3.5
  Top Layer w0.5: P8.1@16.375,76.373 16.401,76.347 P8.1@16.401,76.29 ; RA.2@16.455,72.852 P8.1@16.455,76.293
RFOUT: C107.1 L2.1 U3.B12 | length 2.7
  Top Layer w0.3: U3.B12@16.868,42.688 16.868,43.483
  Top Layer w0.5: C107.1@15.953,44.461 L2.1@16.868,44.461 16.868,43.483
SWCLK: JP1.3 U3.A8 | length 24.9
  Top Layer w0.203: v1(15.755,39.786) 16.053,39.488 U3.A8@16.068,39.488
  Bottom Layer w0.152: JP1.3@3.372,57.079 6.912,57.079 9.907,54.084 9.907,46.657 15.755,40.809 v1(15.755,39.786)
SWDIO: JP1.2 U3.F10 | length 30.2
  Top Layer w0.203: v1(19.668,40.688) U3.F10@20.068,41.088
  Signal Layer 2 w0.152: JP1.2@3.372,59.619 6.578,59.619 8.73,57.466 8.73,49.92 13.699,44.951 17.259,44.951 19.28,42.93 19.28,41.076 v1(19.668,40.688)
V_PA: B3.1 C2.1 C3.2 C4.1 C27.1 C55.1 C68.2 C97.2 C99.2 C100.1 U6.5 U8.11 U8.14 U8.16 | length 34.7
  Top Layer w0.254: C100.1@11.978,55.645 12.853,55.645 13.725,55.645 13.737,55.656 14.607,55.656 14.955,55.309 U8.11@14.955,54.411 ; C3.2@12.56,52.265 12.68,52.144 13.599,52.144 13.741,52.286 U8.16@14.33,52.286
  Top Layer w0.3: C3.2@12.56,52.265 12.564,52.269 C99.2@12.564,53.132 ; 13.704,53.295 13.713,53.286 U8.14@14.33,53.286
  Top Layer w0.5: C55.1@12.854,55.645 C55.1@12.858,55.641 ; C27.1@30.084,54.973 B3.1@30.084,54.033 30.088,54.037 U6.5@32.532,54.037
  Bottom Layer w0.8: 11.655,53.343 11.655,51.753 14.491,48.917 18.471,48.917 24.604,55.05 29.68,55.05 30.054,54.676
  other v1: 12.558,53.63 13.158,53.63 30.268,53.619 30.783,53.619 12.858,53.98 30.527,54.032
V_RADIO: B3.2 R33.1 | length 13.7
  Top Layer w0.305: R33.1@20.17,45.375 20.178,45.384 v1(20.178,45.938) ; v1(28.511,53.356) 28.514,53.356 29.188,54.029 B3.2@29.184,54.033
  Bottom Layer w0.305: v1(20.178,45.938) 20.178,47.166 26.368,53.356 v1(28.511,53.356)
VBAT: B5.2 C26.1 C28.1 C67.2 C69.2 P3.13 P3.14 SW1.5 U5.1 U5.3 U6.1 U6.3 | length 62.2
  Top Layer w0.203: U5.1@34.921,49.246 34.903,49.265 34.073,49.265 33.817,49.521 33.817,50.893 34.07,51.146 U5.3@34.921,51.146 ; U6.1@34.932,54.037 34.914,54.019 34.175,54.019 33.886,54.308 33.886,55.74 34.084,55.937 U6.3@34.932,55.937
  Top Layer w0.5: U5.1@34.921,49.246 37.16,49.246 C67.2@37.348,49.435 ; U6.1@34.932,54.037 37.15,54.037 C69.2@37.348,54.236
  Top Layer w0.8: B5.2@32.396,69.107 32.396,71.772 36.514,75.891 SW1.5@41.12,75.891 ; 39.351,49.396 44.965,49.396 ; P3.13@45.79,47.681 44.965,48.505 44.965,49.396 ; P3.14@45.79,50.221 44.965,49.396
  Signal Layer 2 w0.5: v3(38.074,49.398) 38.074,53.655 38.077,53.658
  Signal Layer 2 w0.8: 38.095,55.311 38.095,55.974 36.149,57.92 36.149,66.056 38.954,68.861 38.954,69.372 41.12,71.539 SW1.5@41.12,75.891
  other v1: 38.061,54.062 38.058,54.551
VIN: CON1.1 P7.3 | length 7
  Top Layer w0.8: P7.3@40.497,60.647 40.324,60.473 40.324,56.07 41.135,55.259 42.362,55.259
VOX_DET: R11.1 U3.L1 | length 14.7
  Top Layer w0.203: v1@24.068,33.376 U3.L1@24.068,33.888 ; v1(32.302,23.85) 32.892,23.85 R11.1@32.909,23.868
  Signal Layer 1 w0.152: v1(24.07,33.376) 24.07,30.998 31.218,23.85 v1(32.302,23.85)
WCLK: U3.L10 U9.7 | length 21.7
  Top Layer w0.152: v1(23.668,40.688) U3.L10@24.068,41.088
  Top Layer w0.203: U9.7@36.43,42.794 37.738,42.794 37.997,43.053 v1(38.972,43.053)
  Signal Layer 1 w0.152: v1(23.668,40.688) 24.074,41.095 24.337,41.095 25.13,41.887 25.13,42.725 25.618,43.214 26.721,43.214 27.146,43.638 36.285,43.638 37.849,42.074 38.67,42.074 38.972,42.376 v1(38.972,43.053)
pads on no net: P8.2 U3.E9 U3.H4 U5.4 U6.4 U9.9 U9.11 U9.14 U9.15 U9.25 X1.1
copper on no net:
  other v1: 21.849,13.564 20.287,14.598

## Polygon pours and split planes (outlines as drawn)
GND on Signal Layer 2 "Bottom Layer-No Net" (solid, remove dead copper, pour order 6): 2.074,84.691 2.542,84.222 2.542,4.707
GND on Signal Layer 2 "Bottom Layer-No Net" (solid, remove dead copper, pour order 11): 2.074,84.691 2.074,4.691 47.074,4.691 47.074,84.691
GND on Signal Layer 1 "Bottom Layer-No Net" (solid, remove dead copper, pour order 9): 2.074,84.691 2.074,4.691 47.074,4.691 47.074,84.691
GND on Bottom Layer "Bottom Layer-No Net" (solid, remove dead copper, pour order 13): 2.074,84.691 2.074,4.691 47.074,4.691 47.074,84.691
GND on Top Layer "Bottom Layer-No Net" (solid, remove dead copper, pour order 15): 2.074,84.691 2.074,4.691 47.074,4.691 47.074,84.691

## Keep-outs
Keep-Out Layer:
  lines w0.203: 2.074,4.691 47.074,4.691 47.074,84.691 2.074,84.691 2.074,4.691

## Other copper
Top Layer:
  rectangle net V_PA: 29.831,53.359 31.131,53.824
  rectangle net V_PA: 29.834,53.807 29.834,53.808
  region net GND: 17.798,50.86 18.043,51.105 17.712,51.436 17.468,51.191
  rectangle net GND: 14.895,51.686 16.523,53.837
  rectangle net GND: 16.437,52.636 17.356,53.436
  region net GND: 16.105,53.768 16.105,54.686 15.305,54.686 15.305,53.768
  rectangle net GND: 15.305,51.389 15.605,51.79
  region net GND: 16.846,51.12 16.939,51.212 16.479,51.672 16.387,51.579
  rectangle net GND: 16.305,51.319 16.523,51.707
  region net GND: 14.732,53.69 14.853,53.812 14.361,54.303 14.24,54.182
  rectangle net GND: 14.071,53.636 15.06,53.837
  rectangle net GND: 14.055,53.863 14.605,54.16
  rectangle net GND: 17.259,55.051 18.153,60.7
  region net GND: 18.123,55.433 17.838,55.719 16.805,54.686 17.091,54.4
  region net GND: 15.621,55.17 15.378,54.927 15.862,54.443 16.105,54.686
  rectangle net GND: 15.305,54.686 15.649,60.7
  region net GND: 14.072,51.296 13.279,50.504 13.811,49.972 14.604,50.764
  rectangle net GND: 13.649,49.223 14.489,50.764
  rectangle net GND: 16.82,47.188 18.043,51.105
  region net GND: 17.181,50.605 16.573,51.213 16.334,50.975 16.942,50.366
  rectangle net GND: 16.455,50.973 17.712,51.436
  rectangle net GND: 17.08,54.136 18.005,54.411
  rectangle net GND: 14.33,50.764 14.604,51.161
  rectangle net GND: 13.279,49.347 14.489,50.504
  rectangle net V_PA: 12.31,53.343 13.376,55.641
  region net V_PA: 13.621,53.171 13.875,53.425 13.316,53.984 13.062,53.73
  rectangle net V_PA: 13.376,53.343 13.376,53.343
  rectangle net V_PA: 13.376,53.343 13.456,53.417
  rectangle net GND: 9.895,56.324 15.649,60.7
  rectangle net VBAT: 37.635,53.787 38.348,54.6
  rectangle net VBAT: 37.628,48.995 39.593,49.809
  region net VIN: 43.02,55.352 42.85,55.521 42.441,55.113 42.611,54.943
  rectangle net VBAT: 37.752,54.6 38.348,54.804
  rectangle net GND: 2.239,43.673 9.825,46.203
  rectangle net GND: 2.239,50.604 9.879,52.019
  rectangle net GND: 45.037,72.651 45.335,74.854
  region net GND: 46.766,73.629 46.766,73.926 43.684,73.926 43.684,73.629
Signal Layer 1:
  region net GND: 42.963,7.565 42.963,7.862 41.019,7.862 41.019,7.565
  rectangle net GND: 41.816,6.762 42.114,8.708
  rectangle net GND: 32.081,79.958 32.379,81.904
  region net GND: 33.228,80.761 33.228,81.059 31.285,81.059 31.285,80.761
  region net GND: 46.766,73.629 46.766,73.926 43.529,73.926 43.529,73.629
  rectangle net GND: 45.037,72.651 45.335,74.854
  rectangle net GND: 44.091,58.786 46.909,61.04
  rectangle net GND: 44.19,52.357 46.909,54.786
Signal Layer 2:
  rectangle net VBAT: 37.693,53.557 38.497,55.311
  region net GND: 42.963,7.565 42.963,7.862 41.019,7.862 41.019,7.565
  rectangle net GND: 41.816,6.762 42.114,8.708
  rectangle net GND: 45.037,72.651 45.335,74.854
  region net GND: 46.766,73.629 46.766,73.926 43.529,73.926 43.529,73.629
Bottom Layer:
  rectangle net V_PA: 11.254,53.349 13.427,54.269
  region net V_PA: 30.401,53.706 31.013,54.318 30.385,54.946 29.773,54.334
  rectangle net V_PA: 30.048,53.353 31.013,54.318
  rectangle net GND: 41.816,6.762 42.114,8.708
  region net GND: 42.963,7.565 42.963,7.862 41.019,7.862 41.019,7.565
  region net GND: 33.228,80.761 33.228,81.059 31.285,81.059 31.285,80.761
  rectangle net GND: 32.081,79.958 32.379,81.904
  region net GND: 46.753,73.629 46.753,73.926 43.523,73.926 43.523,73.629
  rectangle net GND: 45.037,72.663 45.335,74.857
  rectangle net GND: 45.191,58.533 45.937,60.902
  region net GND: 46.075,59.406 46.075,60.152 43.707,60.152 43.707,59.406
  region net GND: 46.075,53.406 46.075,54.152 43.707,54.152 43.707,53.406
  rectangle net GND: 45.191,52.533 45.937,54.902
  region net GND: 33.503,66.57 33.334,66.738 33.128,66.532 33.297,66.364

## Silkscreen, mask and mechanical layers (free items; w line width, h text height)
Top Overlay:
  region: 7.876,27.934 7.876,22.016 18.694,22.016 18.694,27.934
  region: 17.642,29.407 17.642,22.016 31.269,22.016 31.269,29.407
  lines w0.203: 7.521,21.686 7.521,29.686 31.521,29.686 31.521,21.686 7.521,21.686 ; 9.574,30.313 40.574,30.313 40.574,59.313 9.574,59.313 9.574,30.313
  text "+" at 46.482,66.767 h1.27 r90
  text "DC" at 36.604,65.182 h1
  text "-" at 46.556,61.229 h1.27 r90
  text "USB" at 35.898,60.169 h1
  text "SPK+" at 31.721,59.708 h1 r90
  text "SPK-" at 34.68,59.708 h1 r90
  text "Serial Number" at 7.976,28.248 h1
  text "SCT2400EVM V2.0" at 14.464,13.524 h1
  text "+" at 37.173,8.617 h0.5
  text "+" at 34.163,8.579 h0.5
Bottom Overlay:
  text "D3V3_D" at 10.414,61.629 h1
  text "SWDIO" at 9.201,59.08 h1
  text "SWCLK" at 9.709,56.617 h1
  text "GND" at 7.914,54.017 h1
  text "VBAT" at 43.993,49.661 h1
  text "VBAT" at 43.98,47.061 h1
  text "PD14" at 43.993,44.623 h1
  text "PD9" at 44.005,42.136 h1
  text "GND" at 7.728,41.715 h1
  text "PD8" at 44.018,39.598 h1
  text "PA10" at 8.1,39.177 h1
  text "PD12" at 44.03,37.049 h1
  text "PA9" at 7.691,36.64 h1
  text "PD10" at 44.03,34.462 h1
  text "PB3" at 7.716,34.066 h1
  text "PD15" at 44.042,31.961 h1
  text "PD5" at 7.728,31.603 h1
  text "PE11" at 44.043,29.449 h1
  text "PD6" at 7.728,29.016 h1
  text "PE10" at 44.055,26.813 h1
  text "PD7" at 7.703,26.478 h1
  text "PD11" at 44.043,24.362 h1
  text "PB5" at 7.703,23.953 h1
  text "PE9" at 44.043,21.849 h1
  text "PB2" at 34.574,21.775 h1 r270
  text "GND" at 37.086,21.75 h1 r270
  text "PA6" at 26.913,21.726 h1 r270
  text "PC4" at 29.487,21.726 h1 r270
  text "PE12" at 31.963,21.738 h1 r270
  text "PC1" at 19.387,21.701 h1 r270
  text "PA0" at 21.9,21.701 h1 r270
  text "PA1" at 24.4,21.713 h1 r270
  text "PB8" at 11.738,21.664 h1 r270
  text "PE4" at 14.214,21.664 h1 r270
  text "PC14" at 16.763,21.676 h1 r270
  text "GND" at 9.189,21.602 h1 r270
  text "PB7" at 7.703,21.391 h1
  text "PE7" at 44.055,19.337 h1
  text "PB4" at 7.678,18.963 h1
  text "GND" at 44.08,16.738 h1
  text "PB6" at 7.69,16.33 h1
  text "PB9" at 7.665,13.808 h1
  text "PE3" at 11.751,12.889 h1 r270
  text "PE5" at 14.35,12.889 h1 r270
  text "GND" at 9.238,12.728 h1 r270
  text "PC0" at 21.925,12.505 h1 r270
  text "PA5" at 27.073,12.505 h1 r270
  text "PC2" at 19.34,12.486 h1 r270
  text "PA2" at 24.474,12.493 h1 r270
  text "PA7" at 29.611,12.48 h1 r270
  text "PE8" at 32.074,12.468 h1 r270
  text "PC5" at 34.648,12.468 h1 r270
  text "GND" at 37.248,12.468 h1 r270
  text "PC15" at 16.838,11.836 h1 r270
  text "PE1" at 7.517,11.311 h1
  text "GND" at 7.555,8.804 h1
